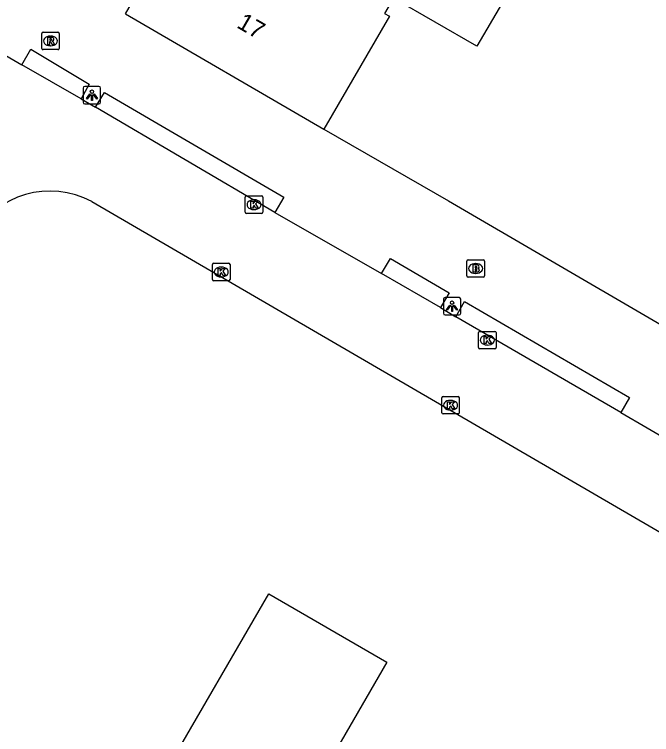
# Model space of a CAD drawing. Extents: x 156502 to 159074, y 384229 to 386094.
# Drawn here: x 157201.27 to 157237.69, y 385827.46 to 385868.64 of the extents above; entities that cross this region are included whole.
import ezdxf

# ---------------------------------------------------------------- set-up
doc = ezdxf.new("R2010")
doc.units = 0
for name, color, linetype in [('IMGEO_Brandkraan', 7, 'Continuous'), ('IMGEO_Hek', 7, 'Continuous'), ('IMGEO_Kolk', 7, 'Continuous'), ('IMGEO_Lichtpunt', 7, 'Continuous'), ('IMGEO_Pand', 7, 'Continuous'), ('IMGEO_Pand_nummerreeks', 7, 'Continuous'), ('IMGEO_Pand_vergunning_verleend', 7, 'Continuous'), ('IMGEO_Rijbaan_lokaal_open', 7, 'Continuous'), ('IMGEO_Rioolput', 7, 'Continuous'), ('IMGEO_Voetpad_open', 7, 'Continuous')]:
    doc.layers.add(name, color=color, linetype=linetype)

msp = doc.modelspace()

# ---------------------------------------------------------------- linework, layer by layer
at = {"layer": 'IMGEO_Brandkraan'}
for p, q in [((157227.135, 385853.685), (157227.135, 385854.537)), ((157227.21, 385854.611), (157228.062, 385854.611)), ((157227.623, 385854.391), (157227.648, 385854.391)), ((157228.136, 385854.537), (157228.136, 385853.685)), ((157228.062, 385853.611), (157227.21, 385853.611)), ((157227.646, 385853.831), (157227.621, 385853.831))]:
    msp.add_line(p, q, dxfattribs=at)
for points in [[(157227.135, 385853.685), (157227.135, 385854.537)], [(157227.21, 385854.611), (157228.062, 385854.611)], [(157228.136, 385854.537), (157228.136, 385853.685)], [(157227.483, 385854.311), (157227.483, 385853.911), (157227.696, 385853.911)], [(157227.714, 385854.311), (157227.483, 385854.311)], [(157227.662, 385854.23), (157227.608, 385854.23), (157227.608, 385854.154)], [(157227.608, 385854.154), (157227.661, 385854.154)], [(157227.67, 385854.078), (157227.608, 385854.078), (157227.608, 385853.997)], [(157227.608, 385853.997), (157227.67, 385853.997)], [(157228.062, 385853.611), (157227.21, 385853.611)]]:
    msp.add_lwpolyline(points, dxfattribs=at)
for centre, radius, start, end in [((157227.212, 385854.535), 0.0765, 91.552, 178.448), ((157227.212, 385854.535), 0.0765, 91.552, 178.448), ((157228.06, 385854.535), 0.0765, 1.552, 88.448), ((157228.06, 385854.535), 0.0765, 1.552, 88.448), ((157227.663, 385854.192), 0.0379, 267.8285, 90.9355), ((157227.671, 385854.037), 0.0404, 269.8759, 90.5077), ((157227.702, 385854.162), 0.251, 268.6676, 293.5347), ((157227.718, 385854.166), 0.145, 59.4692, 91.5367), ((157227.743, 385854.213), 0.0922, 285.5137, 58.1501), ((157227.748, 385854.021), 0.105, 301.3115, 78.989), ((157227.212, 385853.687), 0.0765, 181.552, 268.448), ((157227.212, 385853.687), 0.0765, 181.552, 268.448), ((157228.06, 385853.687), 0.0765, 271.552, 358.448), ((157228.06, 385853.687), 0.0765, 271.552, 358.448)]:
    msp.add_arc(centre, radius, start, end, dxfattribs=at)
for centre, major_axis, ratio, start_param, end_param in [((157227.622, 385854.111), (-0.387, 0.002), 0.722429, 4.712389, 7.853982), ((157227.647, 385854.111), (-0.39, 0.002), 0.717154, 1.570796, 4.712389)]:
    msp.add_ellipse(centre, major_axis=major_axis, ratio=ratio, start_param=start_param, end_param=end_param, dxfattribs=at)
at = {"layer": 'IMGEO_Hek'}
msp.add_lwpolyline([(157218.954, 385862.085), (157226.078, 385857.975)], dxfattribs=at)
at = {"layer": 'IMGEO_Kolk'}
for p, q in [((157214.468, 385857.336), (157214.468, 385858.188)), ((157214.543, 385858.262), (157215.395, 385858.262)), ((157214.956, 385858.042), (157214.981, 385858.042)), ((157215.469, 385858.188), (157215.469, 385857.336)), ((157215.395, 385857.262), (157214.543, 385857.262)), ((157214.979, 385857.482), (157214.954, 385857.482)), ((157212.596, 385853.485), (157212.596, 385854.337)), ((157212.671, 385854.411), (157213.523, 385854.411)), ((157213.597, 385854.337), (157213.597, 385853.485)), ((157213.084, 385854.191), (157213.109, 385854.191)), ((157213.107, 385853.631), (157213.082, 385853.631)), ((157213.523, 385853.411), (157212.671, 385853.411)), ((157227.802, 385849.59), (157227.802, 385850.442)), ((157227.877, 385850.516), (157228.729, 385850.516)), ((157228.29, 385850.296), (157228.315, 385850.296)), ((157228.803, 385850.442), (157228.803, 385849.59)), ((157228.729, 385849.516), (157227.877, 385849.516)), ((157228.313, 385849.736), (157228.288, 385849.736)), ((157225.702, 385845.866), (157225.702, 385846.718)), ((157225.777, 385846.792), (157226.629, 385846.792)), ((157226.19, 385846.572), (157226.215, 385846.572)), ((157226.703, 385846.718), (157226.703, 385845.866)), ((157226.629, 385845.792), (157225.777, 385845.792)), ((157226.213, 385846.012), (157226.188, 385846.012))]:
    msp.add_line(p, q, dxfattribs=at)
for points in [[(157214.468, 385857.336), (157214.468, 385858.188)], [(157214.543, 385858.262), (157215.395, 385858.262)], [(157215.469, 385858.188), (157215.469, 385857.336)], [(157214.789, 385857.962), (157214.912, 385857.962), (157214.912, 385857.811), (157215.042, 385857.962), (157215.206, 385857.962), (157215.06, 385857.811), (157215.213, 385857.562), (157215.061, 385857.562), (157214.976, 385857.726), (157214.912, 385857.659), (157214.912, 385857.562), (157214.789, 385857.562), (157214.789, 385857.962)], [(157215.395, 385857.262), (157214.543, 385857.262)], [(157212.596, 385853.485), (157212.596, 385854.337)], [(157212.671, 385854.411), (157213.523, 385854.411)], [(157213.597, 385854.337), (157213.597, 385853.485)], [(157212.917, 385854.111), (157213.04, 385854.111), (157213.04, 385853.96), (157213.17, 385854.111), (157213.334, 385854.111), (157213.188, 385853.96), (157213.341, 385853.711), (157213.189, 385853.711), (157213.104, 385853.875), (157213.04, 385853.808), (157213.04, 385853.711), (157212.917, 385853.711), (157212.917, 385854.111)], [(157213.523, 385853.411), (157212.671, 385853.411)], [(157227.802, 385849.59), (157227.802, 385850.442)], [(157227.877, 385850.516), (157228.729, 385850.516)], [(157228.123, 385850.216), (157228.246, 385850.216), (157228.246, 385850.065), (157228.376, 385850.216), (157228.54, 385850.216), (157228.394, 385850.065), (157228.547, 385849.816), (157228.395, 385849.816), (157228.31, 385849.98), (157228.246, 385849.913), (157228.246, 385849.816), (157228.123, 385849.816), (157228.123, 385850.216)], [(157228.803, 385850.442), (157228.803, 385849.59)], [(157228.729, 385849.516), (157227.877, 385849.516)], [(157225.702, 385845.866), (157225.702, 385846.718)], [(157225.777, 385846.792), (157226.629, 385846.792)], [(157226.703, 385846.718), (157226.703, 385845.866)], [(157226.023, 385846.492), (157226.146, 385846.492), (157226.146, 385846.341), (157226.276, 385846.492), (157226.44, 385846.492), (157226.294, 385846.341), (157226.447, 385846.092), (157226.295, 385846.092), (157226.21, 385846.256), (157226.146, 385846.189), (157226.146, 385846.092), (157226.023, 385846.092), (157226.023, 385846.492)], [(157226.629, 385845.792), (157225.777, 385845.792)]]:
    msp.add_lwpolyline(points, dxfattribs=at)
for centre, start, end in [((157214.545, 385858.186), 91.552, 178.448), ((157214.545, 385858.186), 91.552, 178.448), ((157215.393, 385858.186), 1.552, 88.448), ((157215.393, 385858.186), 1.552, 88.448), ((157214.545, 385857.338), 181.552, 268.448), ((157214.545, 385857.338), 181.552, 268.448), ((157215.393, 385857.338), 271.552, 358.448), ((157215.393, 385857.338), 271.552, 358.448), ((157212.673, 385854.335), 91.552, 178.448), ((157212.673, 385854.335), 91.552, 178.448), ((157213.521, 385854.335), 1.552, 88.448), ((157213.521, 385854.335), 1.552, 88.448), ((157212.673, 385853.487), 181.552, 268.448), ((157212.673, 385853.487), 181.552, 268.448), ((157213.521, 385853.487), 271.552, 358.448), ((157213.521, 385853.487), 271.552, 358.448), ((157227.879, 385850.44), 91.552, 178.448), ((157227.879, 385850.44), 91.552, 178.448), ((157228.727, 385850.44), 1.552, 88.448), ((157228.727, 385850.44), 1.552, 88.448), ((157227.879, 385849.592), 181.552, 268.448), ((157227.879, 385849.592), 181.552, 268.448), ((157228.727, 385849.592), 271.552, 358.448), ((157228.727, 385849.592), 271.552, 358.448), ((157225.779, 385846.716), 91.552, 178.448), ((157225.779, 385846.716), 91.552, 178.448), ((157226.627, 385846.716), 1.552, 88.448), ((157226.627, 385846.716), 1.552, 88.448), ((157225.779, 385845.868), 181.552, 268.448), ((157225.779, 385845.868), 181.552, 268.448), ((157226.627, 385845.868), 271.552, 358.448), ((157226.627, 385845.868), 271.552, 358.448)]:
    msp.add_arc(centre, 0.0765, start, end, dxfattribs=at)
for centre, major_axis, ratio, start_param, end_param in [((157214.955, 385857.762), (-0.387, 0.002), 0.722429, 4.712389, 7.853982), ((157214.98, 385857.762), (-0.39, 0.002), 0.717154, 1.570796, 4.712389), ((157213.083, 385853.911), (-0.387, 0.002), 0.722429, 4.712389, 7.853982), ((157213.108, 385853.911), (-0.39, 0.002), 0.717154, 1.570796, 4.712389), ((157228.289, 385850.016), (-0.387, 0.002), 0.722429, 4.712389, 7.853982), ((157228.314, 385850.016), (-0.39, 0.002), 0.717154, 1.570796, 4.712389), ((157226.189, 385846.292), (-0.387, 0.002), 0.722429, 4.712389, 7.853982), ((157226.214, 385846.292), (-0.39, 0.002), 0.717154, 1.570796, 4.712389)]:
    msp.add_ellipse(centre, major_axis=major_axis, ratio=ratio, start_param=start_param, end_param=end_param, dxfattribs=at)
at = {"layer": 'IMGEO_Lichtpunt'}
for p, q in [((157205.205, 385864.426), (157205.205, 385863.619)), ((157205.205, 385864.426), (157205.205, 385863.619)), ((157206.107, 385864.521), (157205.299, 385864.521)), ((157206.107, 385864.521), (157205.299, 385864.521)), ((157206.201, 385863.619), (157206.201, 385864.426)), ((157206.201, 385863.619), (157206.201, 385864.426)), ((157205.299, 385863.525), (157206.107, 385863.525)), ((157205.299, 385863.525), (157206.107, 385863.525)), ((157225.79, 385852.355), (157225.79, 385851.548)), ((157225.79, 385852.355), (157225.79, 385851.548)), ((157226.692, 385852.45), (157225.884, 385852.45)), ((157226.692, 385852.45), (157225.884, 385852.45)), ((157226.786, 385851.548), (157226.786, 385852.355)), ((157226.786, 385851.548), (157226.786, 385852.355)), ((157225.884, 385851.454), (157226.692, 385851.454)), ((157225.884, 385851.454), (157226.692, 385851.454))]:
    msp.add_line(p, q, dxfattribs=at)
for points in [[(157205.579, 385864.09), (157205.618, 385864.062), (157205.43, 385863.8), (157205.392, 385863.827), (157205.579, 385864.09)], [(157205.681, 385864.042), (157205.728, 385864.042), (157205.728, 385863.72), (157205.681, 385863.72), (157205.681, 385864.042)], [(157205.791, 385864.062), (157205.829, 385864.089), (157206.016, 385863.827), (157205.977, 385863.799), (157205.791, 385864.062)], [(157226.164, 385852.019), (157226.203, 385851.991), (157226.015, 385851.729), (157225.977, 385851.756), (157226.164, 385852.019)], [(157226.266, 385851.971), (157226.313, 385851.971), (157226.313, 385851.649), (157226.266, 385851.649), (157226.266, 385851.971)], [(157226.376, 385851.991), (157226.414, 385852.018), (157226.601, 385851.756), (157226.562, 385851.728), (157226.376, 385851.991)]]:
    msp.add_lwpolyline(points, dxfattribs=at)
for centre in [(157205.704, 385864.224), (157226.289, 385852.153)]:
    msp.add_circle(centre, 0.0994, dxfattribs=at)
for centre, start, end in [((157205.299, 385864.426), 90, 180), ((157205.299, 385864.426), 90, 180), ((157206.107, 385864.426), 0, 90), ((157206.107, 385864.426), 0, 90), ((157205.299, 385863.619), 180, 270), ((157205.299, 385863.619), 180, 270), ((157206.107, 385863.619), 270, 0), ((157206.107, 385863.619), 270, 360), ((157225.884, 385852.355), 90, 180), ((157225.884, 385852.355), 90, 180), ((157226.692, 385852.355), 0, 90), ((157226.692, 385852.355), 0, 90), ((157225.884, 385851.548), 180, 270), ((157225.884, 385851.548), 180, 270), ((157226.692, 385851.548), 270, 0), ((157226.692, 385851.548), 270, 360)]:
    msp.add_arc(centre, 0.0946, start, end, dxfattribs=at)
at = {"layer": 'IMGEO_Pand'}
for points in [[(157207.627, 385868.664), (157211.365, 385875.15), (157211.978, 385874.797), (157212.478, 385875.666), (157210.745, 385876.665), (157214.5, 385883.18), (157214.812, 385883), (157214.732, 385882.862), (157218.418, 385880.738), (157218.498, 385880.877), (157218.81, 385880.697), (157216.482, 385876.657), (157221.993, 385873.482), (157224.899, 385878.267), (157231.916, 385874.005), (157227.702, 385866.82), (157222.95, 385869.578), (157222.433, 385868.694), (157222.709, 385868.533), (157218.954, 385862.085)], [(157207.627, 385868.664), (157218.954, 385862.085)]]:
    msp.add_lwpolyline(points, dxfattribs=at)
at = {"layer": 'IMGEO_Pand_vergunning_verleend'}
msp.add_lwpolyline([(157209.892, 385825.287), (157215.806, 385835.51), (157222.569, 385831.597), (157216.642, 385821.353)], dxfattribs=at)
at = {"layer": 'IMGEO_Rijbaan_lokaal_open'}
for points in [[(157193.644, 385870.453), (157201.692, 385865.761)], [(157205.084, 385863.813), (157201.692, 385865.761)], [(157205.084, 385863.813), (157205.901, 385863.335)], [(157216.161, 385857.317), (157205.901, 385863.335)], [(157205.703, 385857.935), (157250.457, 385831.882), (157250.702, 385832.309)], [(157216.161, 385857.317), (157222.254, 385853.823)], [(157225.619, 385851.871), (157222.254, 385853.823)], [(157225.619, 385851.871), (157226.506, 385851.343)], [(157235.934, 385845.88), (157226.506, 385851.343)], [(157235.934, 385845.88), (157241.947, 385842.373)]]:
    msp.add_lwpolyline(points, dxfattribs=at)
msp.add_arc((157203.316, 385853.505), 5.032, 61.6859, 150.8112, dxfattribs=at)
at = {"layer": 'IMGEO_Rioolput'}
for p, q in [((157202.834, 385866.696), (157202.834, 385867.548)), ((157202.909, 385867.622), (157203.761, 385867.622)), ((157203.835, 385867.548), (157203.835, 385866.696)), ((157203.322, 385867.402), (157203.347, 385867.402)), ((157203.345, 385866.842), (157203.32, 385866.842)), ((157203.761, 385866.622), (157202.909, 385866.622))]:
    msp.add_line(p, q, dxfattribs=at)
for points in [[(157202.834, 385866.696), (157202.834, 385867.548)], [(157202.909, 385867.622), (157203.761, 385867.622)], [(157203.835, 385867.548), (157203.835, 385866.696)], [(157203.423, 385867.32), (157203.171, 385867.322), (157203.171, 385866.922)], [(157203.349, 385867.241), (157203.295, 385867.241), (157203.295, 385867.16)], [(157203.295, 385867.16), (157203.347, 385867.16)], [(157203.171, 385866.922), (157203.295, 385866.922), (157203.295, 385867.084), (157203.306, 385867.084)], [(157203.353, 385867.055), (157203.424, 385866.922), (157203.564, 385866.922), (157203.499, 385867.048)], [(157203.761, 385866.622), (157202.909, 385866.622)]]:
    msp.add_lwpolyline(points, dxfattribs=at)
for centre, radius, start, end in [((157202.911, 385867.546), 0.0765, 91.552, 178.448), ((157202.911, 385867.546), 0.0765, 91.552, 178.448), ((157203.759, 385867.546), 0.0765, 1.552, 88.448), ((157203.759, 385867.546), 0.0765, 1.552, 88.448), ((157203.331, 385867.349), 0.19, 274.7715, 282.9687), ((157203.355, 385867.145), 0.0964, 77.0061, 93.1865), ((157203.369, 385867.202), 0.0378, 276.6634, 79.6772), ((157203.422, 385867.21), 0.109, 350.3612, 89.416), ((157203.42, 385867.21), 0.112, 277.5842, 350.9817), ((157203.404, 385866.995), 0.108, 29.5134, 73.7905), ((157202.911, 385866.698), 0.0765, 181.552, 268.448), ((157202.911, 385866.698), 0.0765, 181.552, 268.448), ((157203.305, 385867.031), 0.0533, 26.0293, 88.6989), ((157203.759, 385866.698), 0.0765, 271.552, 358.448), ((157203.759, 385866.698), 0.0765, 271.552, 358.448)]:
    msp.add_arc(centre, radius, start, end, dxfattribs=at)
for centre, major_axis, ratio, start_param, end_param in [((157203.321, 385867.122), (-0.387, 0.002), 0.722429, 4.712389, 7.853982), ((157203.346, 385867.122), (-0.39, 0.002), 0.717154, 1.570796, 4.712389)]:
    msp.add_ellipse(centre, major_axis=major_axis, ratio=ratio, start_param=start_param, end_param=end_param, dxfattribs=at)
at = {"layer": 'IMGEO_Voetpad_open'}
for points in [[(157201.692, 385865.761), (157202.208, 385866.645), (157205.541, 385864.654), (157205.084, 385863.813)], [(157205.901, 385863.335), (157206.425, 385864.182), (157216.666, 385858.188), (157216.161, 385857.317)], [(157218.954, 385862.085), (157226.078, 385857.975), (157255.558, 385840.78), (157252.582, 385835.588)], [(157222.254, 385853.823), (157222.769, 385854.683), (157226.118, 385852.71), (157225.619, 385851.871)], [(157226.506, 385851.343), (157227.001, 385852.219), (157236.427, 385846.73), (157235.934, 385845.88)]]:
    msp.add_lwpolyline(points, dxfattribs=at)

# ---------------------------------------------------------------- texts
at = {"layer": 'IMGEO_Pand_nummerreeks'}
msp.add_text('17', height=1, rotation=329.851, dxfattribs=at).set_placement((157213.923, 385867.921))

doc.saveas('drawing.dxf')
